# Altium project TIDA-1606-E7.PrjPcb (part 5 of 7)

## Sheet TIDA-1606-Middle-Side-E7.SchDoc
size A2; Date: Not shown in title block; ApprovedBy: Not shown in title block; CheckedBy: Not shown in title block; Author: Not shown in title block; CompanyName: Not shown in title block; Engineer: Not shown in title block; Organization: Not shown in title block; Address1: Not shown in title block; Address2: Not shown in title block; Address3: Not shown in title block; Address4: Not shown in title block; DocumentNumber: 10; Revision: Use project parameter SCH_Rev; SheetNumber: 10; SheetTotal: 16; PageSetup: Record=PageOptions¦CenterHorizontal=True¦CenterVertical=True¦PrintScale=0.69¦XCorrection=1.00¦YCorrection=1.00¦PrintKind=0¦BorderSize=5000000¦LeftOffset=0¦BottomOffset=0¦Orientation=2¦PaperLength=1000¦PaperWidth=1000¦Scale=100¦PaperSource=15¦PrintQuality=600¦MediaType=1¦DitherType=10¦PaperKind=Letter¦PrintScaleMode=1
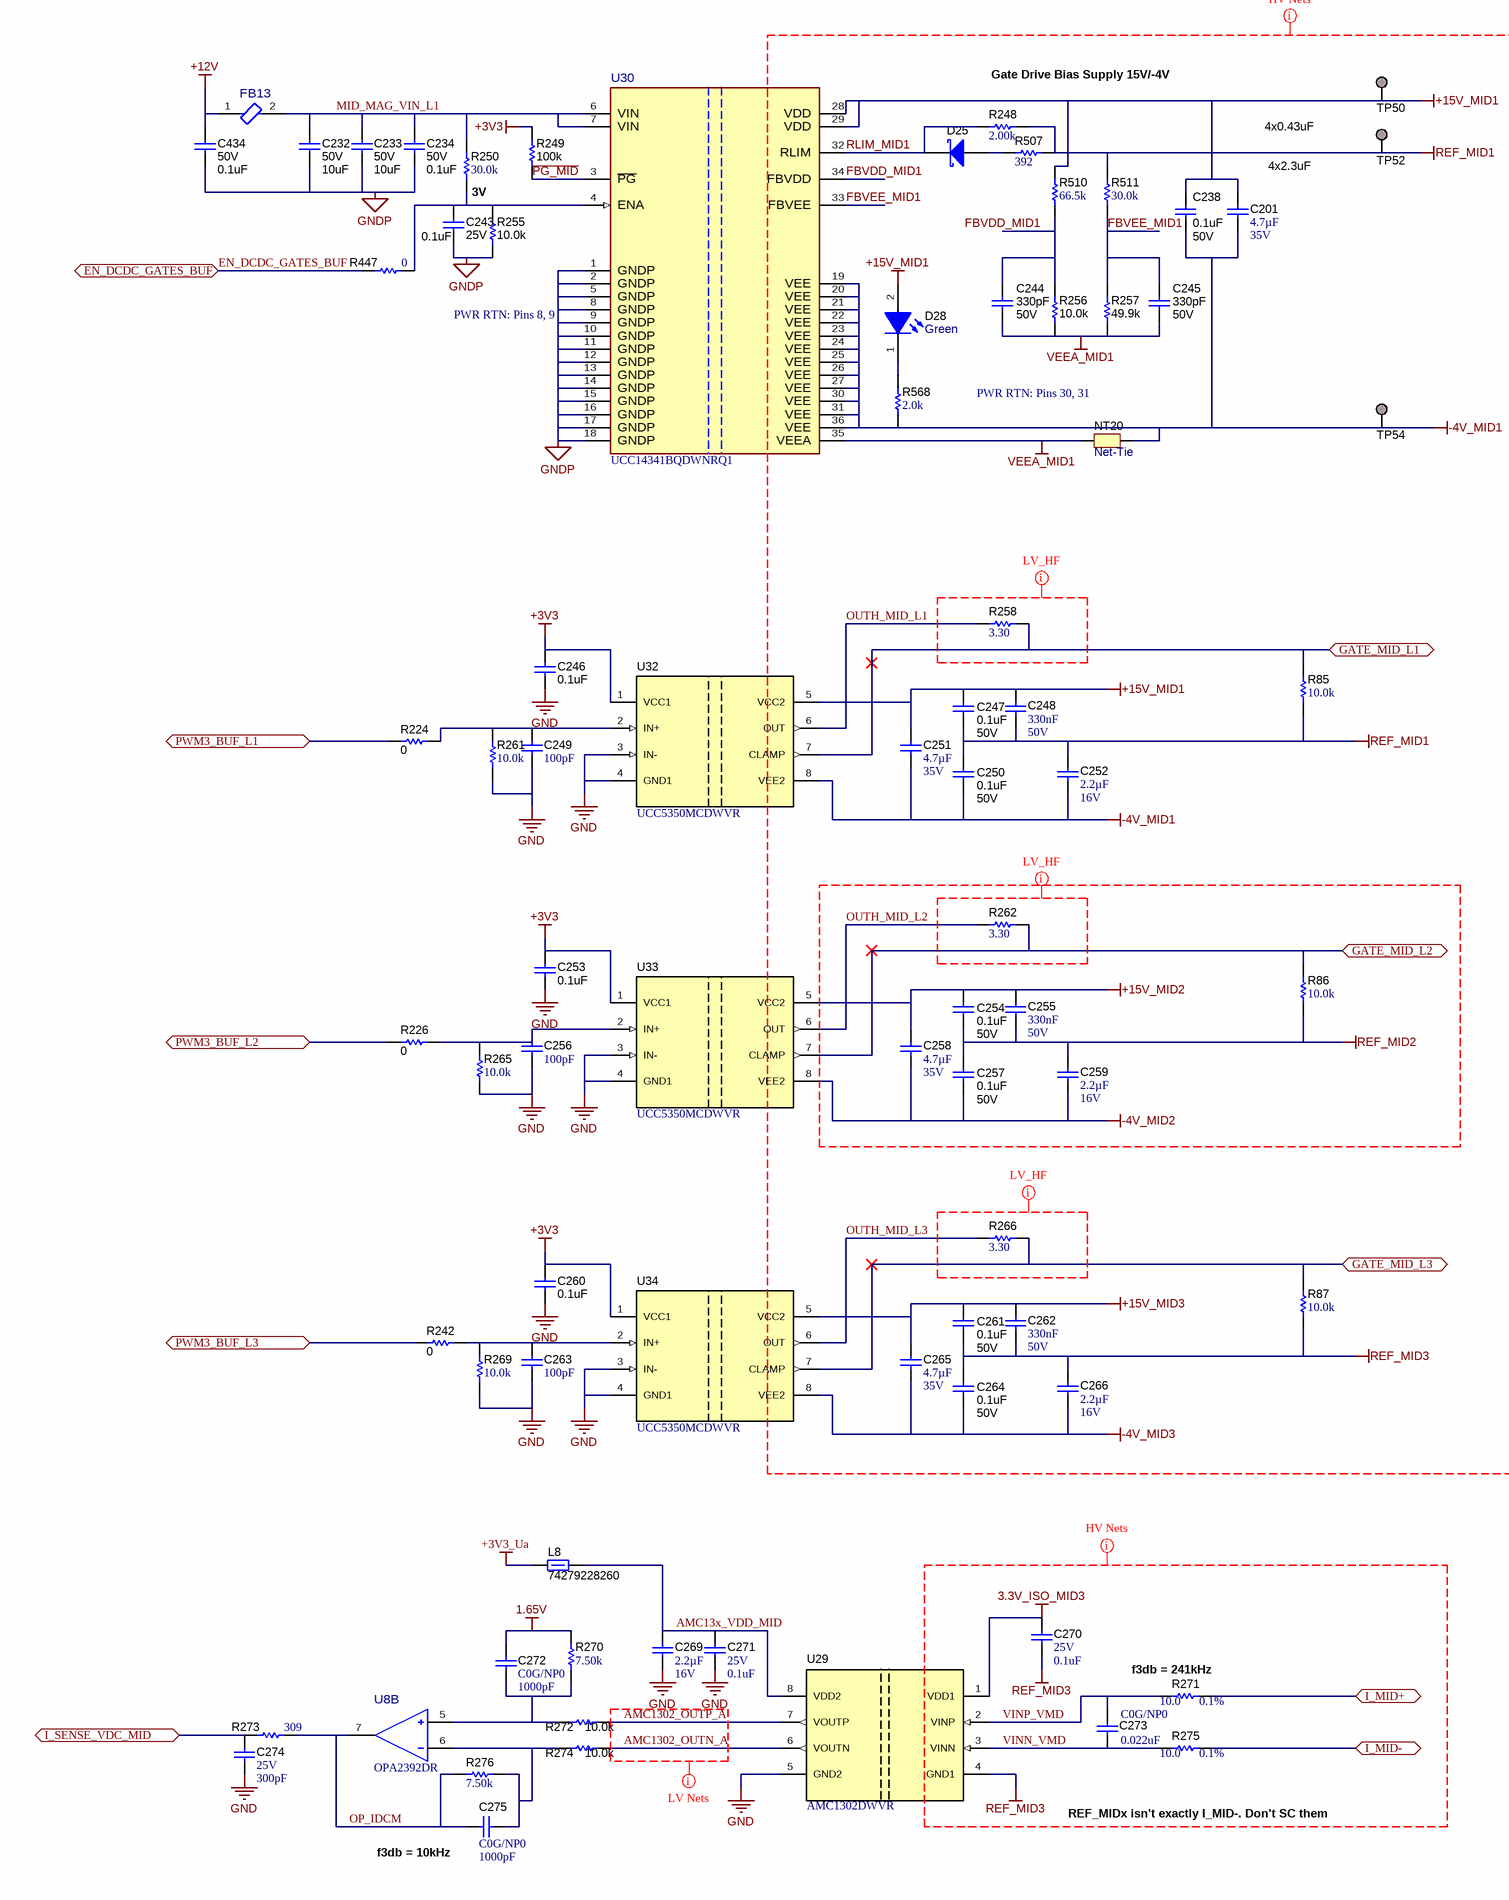
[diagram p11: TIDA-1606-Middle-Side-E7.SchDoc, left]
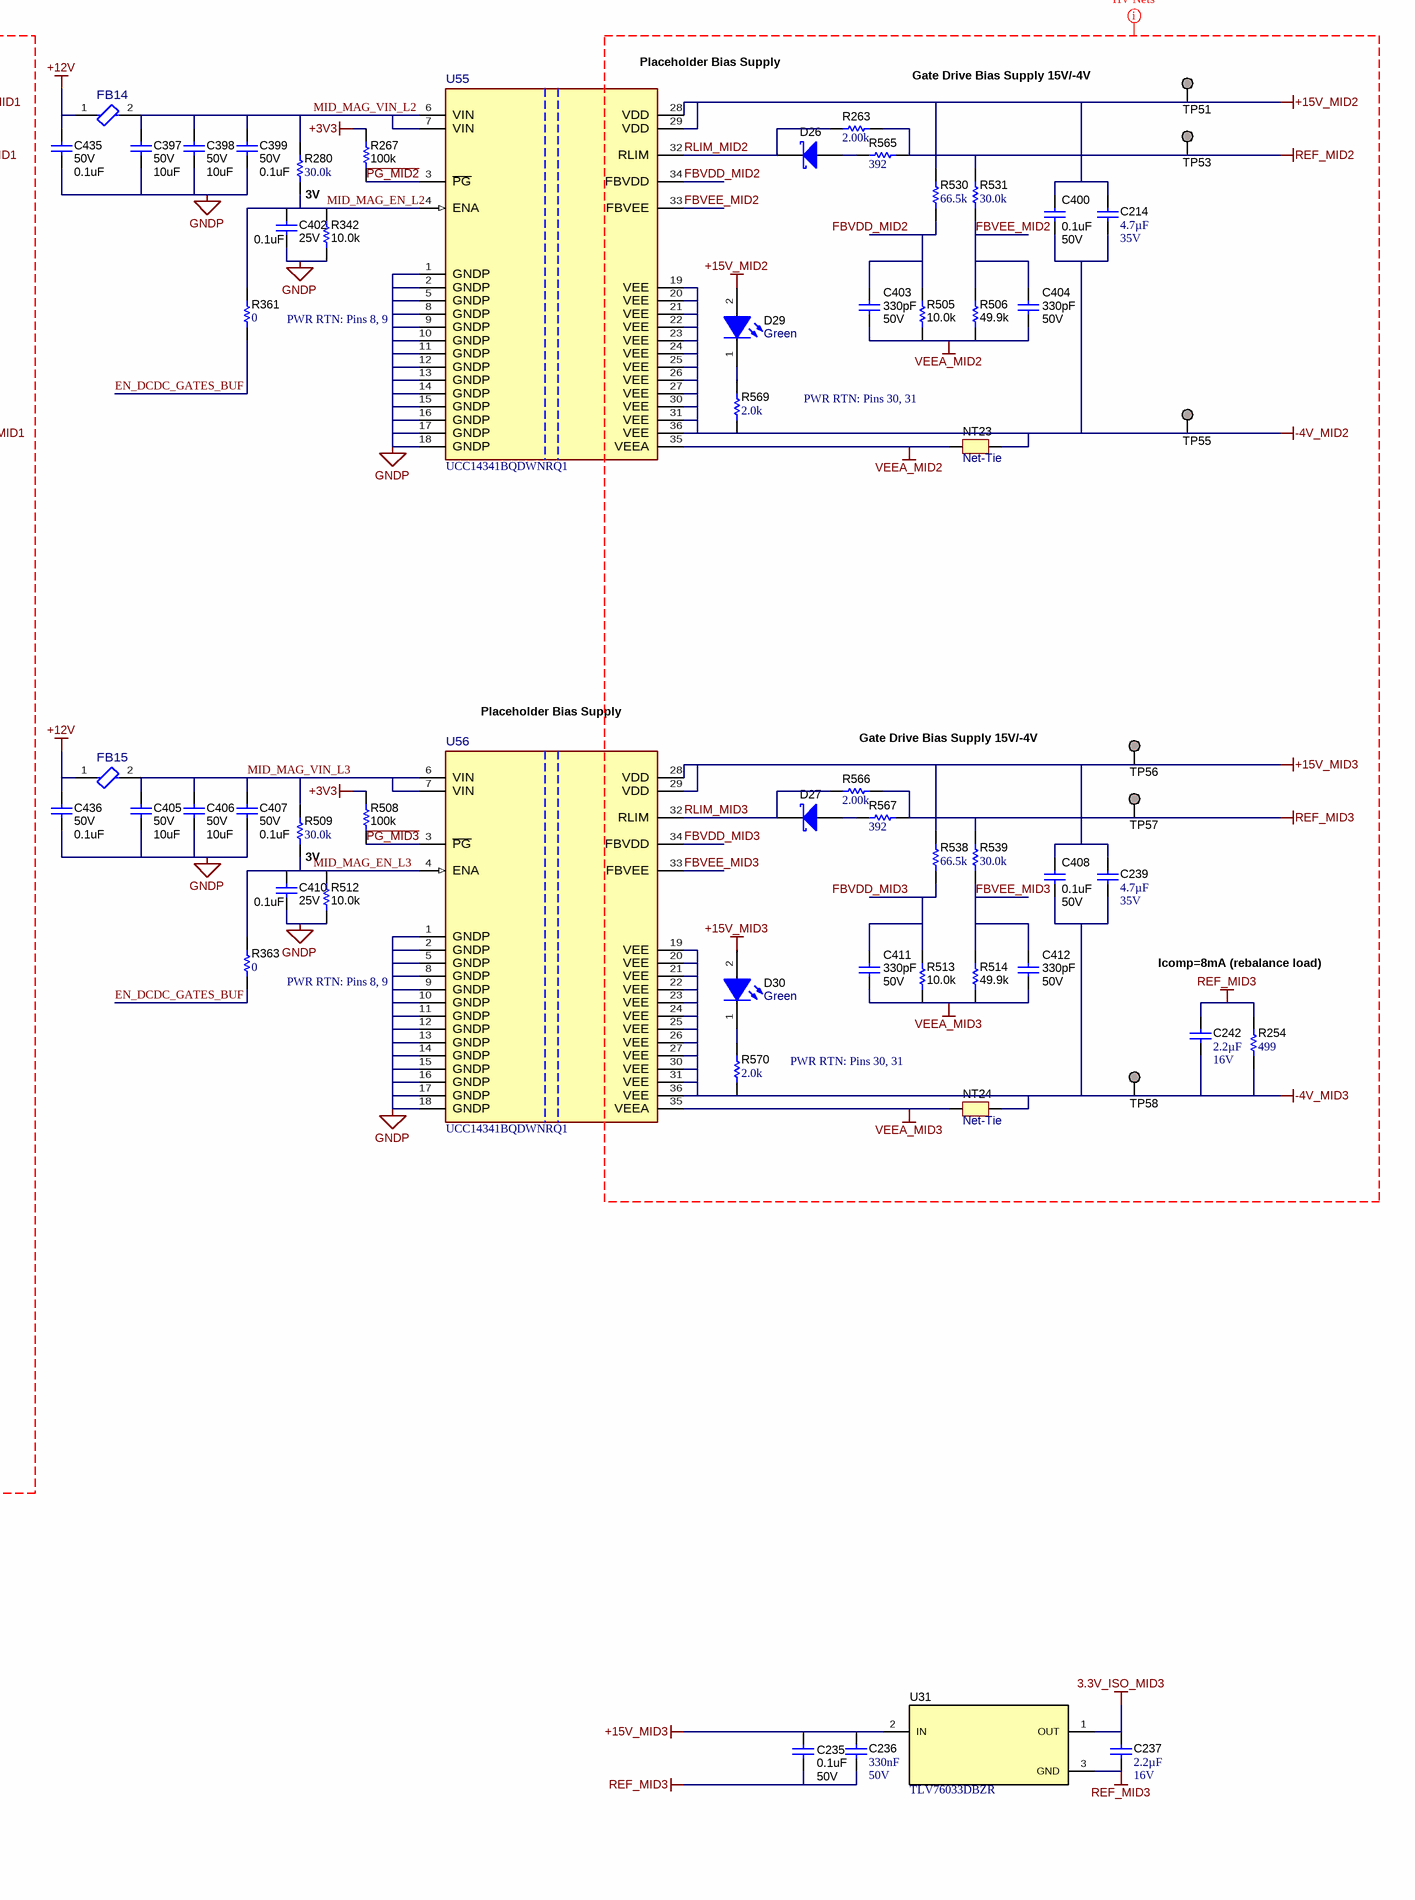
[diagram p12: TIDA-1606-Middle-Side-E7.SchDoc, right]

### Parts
C201  Cap_F: 4.7µF  VDC_V: 35V  [0805_HV]  (hidden comment: C2012X7R1V475K125AC)
C214  Cap_F: 4.7µF  VDC_V: 35V  [0805_HV]  (hidden comment: C2012X7R1V475K125AC)
C232  VDC_V: 50V  ValueDisplayed: 10uF  [1206_180L]  (hidden comment: CL31B106KBHNNNE)
C233  VDC_V: 50V  ValueDisplayed: 10uF  [1206_180L]  (hidden comment: CL31B106KBHNNNE)
C234  VDC_V: 50V  ValueDisplayed: 0.1uF  [0402S]  (hidden comment: GCM155R71H104KE02D)
C235  VDC_V: 50V  ValueDisplayed: 0.1uF  [0402L]  (hidden comment: GCM155R71H104KE02D)
C236  Cap_F: 330nF  VDC_V: 50V  [0603L]  (hidden comment: C1608X7R1H334K080AC)
C237  Cap_F: 2.2µF  VDC_V: 16V  [0603L]  (hidden comment: EMK107BB7225KA-T)
C238  VDC_V: 50V  ValueDisplayed: 0.1uF  [0402L]  (hidden comment: GCM155R71H104KE02D)
C239  Cap_F: 4.7µF  VDC_V: 35V  [0805_HV]  (hidden comment: C2012X7R1V475K125AC)
C242  Cap_F: 2.2µF  VDC_V: 16V  [0603L]  (hidden comment: EMK107BB7225KA-T)
C243  VDC_V: 25V  ValueDisplayed: 0.1uF  [0402S]  (hidden comment: GRM155R71E104KE14D)
C244  VDC_V: 50V  ValueDisplayed: 330pF  [0402S]  (hidden comment: CGA2B2X7R1H331K050BA)
C245  VDC_V: 50V  ValueDisplayed: 330pF  [0402S]  (hidden comment: CGA2B2X7R1H331K050BA)
C246  ValueDisplayed: 0.1uF  [0402L]  (hidden comment: GRM155R61H104ME14D)
C247  VDC_V: 50V  ValueDisplayed: 0.1uF  [0402L]  (hidden comment: GCM155R71H104KE02D)
C248  Cap_F: 330nF  VDC_V: 50V  [0603L]  (hidden comment: C1608X7R1H334K080AC)
C249  ValueDisplayed: 100pF  [0402L]  (hidden comment: GRM1555C1H101JA01D)
C250  VDC_V: 50V  ValueDisplayed: 0.1uF  [0402L]  (hidden comment: GCM155R71H104KE02D)
C251  Cap_F: 4.7µF  VDC_V: 35V  [0805_HV]  (hidden comment: C2012X7R1V475K125AC)
C252  Cap_F: 2.2µF  VDC_V: 16V  [0603L]  (hidden comment: EMK107BB7225KA-T)
C253  ValueDisplayed: 0.1uF  [0402L]  (hidden comment: GRM155R61H104ME14D)
C254  VDC_V: 50V  ValueDisplayed: 0.1uF  [0402L]  (hidden comment: GCM155R71H104KE02D)
C255  Cap_F: 330nF  VDC_V: 50V  [0603L]  (hidden comment: C1608X7R1H334K080AC)
C256  ValueDisplayed: 100pF  [0402L]  (hidden comment: GRM1555C1H101JA01D)
C257  VDC_V: 50V  ValueDisplayed: 0.1uF  [0402L]  (hidden comment: GCM155R71H104KE02D)
C258  Cap_F: 4.7µF  VDC_V: 35V  [0805_HV]  (hidden comment: C2012X7R1V475K125AC)
C259  Cap_F: 2.2µF  VDC_V: 16V  [0603L]  (hidden comment: EMK107BB7225KA-T)
C260  ValueDisplayed: 0.1uF  [0402L]  (hidden comment: GRM155R61H104ME14D)
C261  VDC_V: 50V  ValueDisplayed: 0.1uF  [0402L]  (hidden comment: GCM155R71H104KE02D)
C262  Cap_F: 330nF  VDC_V: 50V  [0603L]  (hidden comment: C1608X7R1H334K080AC)
C263  ValueDisplayed: 100pF  [0402L]  (hidden comment: GRM1555C1H101JA01D)
C264  VDC_V: 50V  ValueDisplayed: 0.1uF  [0402L]  (hidden comment: GCM155R71H104KE02D)
C265  Cap_F: 4.7µF  VDC_V: 35V  [0805_HV]  (hidden comment: C2012X7R1V475K125AC)
C266  Cap_F: 2.2µF  VDC_V: 16V  [0603L]  (hidden comment: EMK107BB7225KA-T)
C269  Cap_F: 2.2µF  VDC_V: 16V  [0603L]  (hidden comment: EMK107BB7225KA-T)
C270  VDC_V: 25V  ValueDisplayed: 0.1uF  [0402L]  (hidden comment: GRM155R71E104KE14D)
C271  VDC_V: 25V  ValueDisplayed: 0.1uF  [0402L]  (hidden comment: GRM155R71E104KE14D)
C272  TempCo: C0G/NP0  ValueDisplayed: 1000pF  [0402L]  (hidden comment: CGA2B2C0G1H102J050BA)
C273  TempCo: C0G/NP0  ValueDisplayed: 0.022uF  [0402L]  (hidden comment: GCM155R71H223KA55D)
C274  VDC_V: 25V  ValueDisplayed: 300pF  [0402L]  (hidden comment: GRM1555C1E301JA01D)
C275  TempCo: C0G/NP0  ValueDisplayed: 1000pF  [0402L]  (hidden comment: CGA2B2C0G1H102J050BA)
C397  VDC_V: 50V  ValueDisplayed: 10uF  [1206_180L]  (hidden comment: CL31B106KBHNNNE)
C398  VDC_V: 50V  ValueDisplayed: 10uF  [1206_180L]  (hidden comment: CL31B106KBHNNNE)
C399  VDC_V: 50V  ValueDisplayed: 0.1uF  [0402S]  (hidden comment: GCM155R71H104KE02D)
C400  VDC_V: 50V  ValueDisplayed: 0.1uF  [0402L]  (hidden comment: GCM155R71H104KE02D)
C402  VDC_V: 25V  ValueDisplayed: 0.1uF  [0402S]  (hidden comment: GRM155R71E104KE14D)
C403  VDC_V: 50V  ValueDisplayed: 330pF  [0402S]  (hidden comment: CGA2B2X7R1H331K050BA)
C404  VDC_V: 50V  ValueDisplayed: 330pF  [0402S]  (hidden comment: CGA2B2X7R1H331K050BA)
C405  VDC_V: 50V  ValueDisplayed: 10uF  [1206_180L]  (hidden comment: CL31B106KBHNNNE)
C406  VDC_V: 50V  ValueDisplayed: 10uF  [1206_180L]  (hidden comment: CL31B106KBHNNNE)
C407  VDC_V: 50V  ValueDisplayed: 0.1uF  [0402S]  (hidden comment: GCM155R71H104KE02D)
C408  VDC_V: 50V  ValueDisplayed: 0.1uF  [0402L]  (hidden comment: GCM155R71H104KE02D)
C410  VDC_V: 25V  ValueDisplayed: 0.1uF  [0402S]  (hidden comment: GRM155R71E104KE14D)
C411  VDC_V: 50V  ValueDisplayed: 330pF  [0402S]  (hidden comment: CGA2B2X7R1H331K050BA)
C412  VDC_V: 50V  ValueDisplayed: 330pF  [0402S]  (hidden comment: CGA2B2X7R1H331K050BA)
C434  VDC_V: 50V  ValueDisplayed: 0.1uF  [0402S]  (hidden comment: GCM155R71H104KE02D)
C435  VDC_V: 50V  ValueDisplayed: 0.1uF  [0402S]  (hidden comment: GCM155R71H104KE02D)
C436  VDC_V: 50V  ValueDisplayed: 0.1uF  [0402S]  (hidden comment: GCM155R71H104KE02D)
D25  NSR0130P2T5G  [SOD-923]  (value not drawn)
D26  NSR0130P2T5G  [SOD-923]  (value not drawn)
D27  NSR0130P2T5G  [SOD-923]  (value not drawn)
D28  value Green  [WL-SMCW_GREEN]  (hidden comment: 150060VS75000)
D29  value Green  [WL-SMCW_GREEN]  (hidden comment: 150060VS75000)
D30  value Green  [WL-SMCW_GREEN]  (hidden comment: 150060VS75000)
FB13  74269244182  [FP-74269244182_0402-MFG]  (value not drawn)
FB14  74269244182  [FP-74269244182_0402-MFG]  (value not drawn)
FB15  74269244182  [FP-74269244182_0402-MFG]  (value not drawn)
L8  74279228260  [0603L]
NT20  Net-Tie  [Net-Tie7milsWide_20milsLong]  (net tie, no BOM)
NT23  Net-Tie  [Net-Tie7milsWide_20milsLong]  (net tie, no BOM)
NT24  Net-Tie  [Net-Tie7milsWide_20milsLong]  (net tie, no BOM)
R85  ValueDisplayed: 10.0k  [0402L]  (hidden comment: CRCW040210K0FKED)
R86  ValueDisplayed: 10.0k  [0402L]  (hidden comment: CRCW040210K0FKED)
R87  ValueDisplayed: 10.0k  [0402L]  (hidden comment: CRCW040210K0FKED)
R224  ValueDisplayed: 0  [0603L]  (hidden comment: RCS06030000Z0EA)
R226  ValueDisplayed: 0  [0603L]  (hidden comment: RCS06030000Z0EA)
R242  ValueDisplayed: 0  [0603L]  (hidden comment: RCS06030000Z0EA)
R248  ValueDisplayed: 2.00k  [0402L]  (hidden comment: CRCW04022K00FKED)
R249  ValueDisplayed: 100k  [0402S]  (hidden comment: ERJ-2GEJ104X)
R250  ValueDisplayed: 30.0k  [0402L]  (hidden comment: CRCW040230K0FKED)
R254  ValueDisplayed: 499  [0805_HV]  (hidden comment: CRCW0805499RFKEA)
R255  ValueDisplayed: 10.0k  [0402S]  (hidden comment: MCS0402MD1002BE100)
R256  ValueDisplayed: 10.0k  [0402S]  (hidden comment: MCS0402MD1002BE100)
R257  ValueDisplayed: 49.9k  [0402S]  (hidden comment: PCF0402-03-49K9BT1)
R258  ValueDisplayed: 3.30  [1206]  (hidden comment: ERJ-8RQF3R3V)
R261  ValueDisplayed: 10.0k  [0402L]  (hidden comment: CRCW040210K0FKED)
R262  ValueDisplayed: 3.30  [1206]  (hidden comment: ERJ-8RQF3R3V)
R263  ValueDisplayed: 2.00k  [0402L]  (hidden comment: CRCW04022K00FKED)
R265  ValueDisplayed: 10.0k  [0402L]  (hidden comment: CRCW040210K0FKED)
R266  ValueDisplayed: 3.30  [1206]  (hidden comment: ERJ-8RQF3R3V)
R267  ValueDisplayed: 100k  [0402S]  (hidden comment: ERJ-2GEJ104X)
R269  ValueDisplayed: 10.0k  [0402L]  (hidden comment: CRCW040210K0FKED)
R270  ValueDisplayed: 7.50k  [0402L]  (hidden comment: ERA-2AEB752X)
R271  Value1: 0.1%  ValueDisplayed: 10.0  [CPF0402]  (hidden comment: CPF0402B10RE1)
R272  ValueDisplayed: 10.0k  [0402L]  (hidden comment: MCS0402MD1002BE100)
R273  ValueDisplayed: 309  [0402L]  (hidden comment: CRCW0402309RFKED)
R274  ValueDisplayed: 10.0k  [0402L]  (hidden comment: MCS0402MD1002BE100)
R275  Value1: 0.1%  ValueDisplayed: 10.0  [CPF0402]  (hidden comment: CPF0402B10RE1)
R276  ValueDisplayed: 7.50k  [0402L]  (hidden comment: ERA-2AEB752X)
R280  ValueDisplayed: 30.0k  [0402L]  (hidden comment: CRCW040230K0FKED)
R342  ValueDisplayed: 10.0k  [0402S]  (hidden comment: MCS0402MD1002BE100)
R361  ValueDisplayed: 0  [0402L]  (hidden comment: RC0402JR-070RL)
R363  ValueDisplayed: 0  [0402L]  (hidden comment: RC0402JR-070RL)
R447  ValueDisplayed: 0  [0402L]  (hidden comment: RC0402JR-070RL)
R505  ValueDisplayed: 10.0k  [0402S]  (hidden comment: MCS0402MD1002BE100)
R506  ValueDisplayed: 49.9k  [0402S]  (hidden comment: PCF0402-03-49K9BT1)
R507  ValueDisplayed: 392  [0402L]  (hidden comment: CRCW0402392RFKED)
R508  ValueDisplayed: 100k  [0402S]  (hidden comment: ERJ-2GEJ104X)
R509  ValueDisplayed: 30.0k  [0402L]  (hidden comment: CRCW040230K0FKED)
R510  ValueDisplayed: 66.5k  [0402L]  (hidden comment: CRCW040266K5FKED)
R511  ValueDisplayed: 30.0k  [0402L]  (hidden comment: CRCW040230K0FKED)
R512  ValueDisplayed: 10.0k  [0402S]  (hidden comment: MCS0402MD1002BE100)
R513  ValueDisplayed: 10.0k  [0402S]  (hidden comment: MCS0402MD1002BE100)
R514  ValueDisplayed: 49.9k  [0402S]  (hidden comment: PCF0402-03-49K9BT1)
R530  ValueDisplayed: 66.5k  [0402L]  (hidden comment: CRCW040266K5FKED)
R531  ValueDisplayed: 30.0k  [0402L]  (hidden comment: CRCW040230K0FKED)
R538  ValueDisplayed: 66.5k  [0402L]  (hidden comment: CRCW040266K5FKED)
R539  ValueDisplayed: 30.0k  [0402L]  (hidden comment: CRCW040230K0FKED)
R565  ValueDisplayed: 392  [0402L]  (hidden comment: CRCW0402392RFKED)
R566  ValueDisplayed: 2.00k  [0402L]  (hidden comment: CRCW04022K00FKED)
R567  ValueDisplayed: 392  [0402L]  (hidden comment: CRCW0402392RFKED)
R568  ValueDisplayed: 2.0k  [1206]  (hidden comment: CRCW12062K00JNEA)
R569  ValueDisplayed: 2.0k  [1206]  (hidden comment: CRCW12062K00JNEA)
R570  ValueDisplayed: 2.0k  [1206]  (hidden comment: CRCW12062K00JNEA)
TP50  S2751-46R  [Harwin_S2751-46R]  (value not drawn)
TP51  S2751-46R  [Harwin_S2751-46R]  (value not drawn)
TP52  S2751-46R  [Harwin_S2751-46R]  (value not drawn)
TP53  S2751-46R  [Harwin_S2751-46R]  (value not drawn)
TP54  S2751-46R  [Harwin_S2751-46R]  (value not drawn)
TP55  S2751-46R  [Harwin_S2751-46R]  (value not drawn)
TP56  S2751-46R  [Harwin_S2751-46R]  (value not drawn)
TP57  S2751-46R  [Harwin_S2751-46R]  (value not drawn)
TP58  S2751-46R  [Harwin_S2751-46R]  (value not drawn)
U8  OPA2392DR  [D0008A-MFG]  (part B of 2)
U29  AMC1302DWVR  [DWV0008A]
U30  UCC14341BQDWNRQ1  [DWN0036A-MFG]
U31  TLV76033DBZR  [DBZ0003A_N]
U32  UCC5350MCDWVR  [DWV0008A]
U33  UCC5350MCDWVR  [DWV0008A]
U34  UCC5350MCDWVR  [DWV0008A]
U55  UCC14341BQDWNRQ1  [DWN0036A-MFG]
U56  UCC14341BQDWNRQ1  [DWN0036A-MFG]

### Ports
EN_DCDC_GATES_BUF (bidir), GATE_MID_L1 (bidir), GATE_MID_L2 (bidir), GATE_MID_L3 (bidir), I_MID+ (bidir), I_MID- (bidir), I_SENSE_VDC_MID (bidir), PWM3_BUF_L1 (bidir), PWM3_BUF_L2 (bidir), PWM3_BUF_L3 (bidir)

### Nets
1.65V: C272.2 R270.2
3.3V_ISO_MID3: C237.1 C270.1 U29.1(VDD1) U31.1(OUT)
+3V3: C246.1 C253.1 C260.1 R249.2 R267.2 R508.2 U32.1(VCC1) U33.1(VCC1) U34.1(VCC1)
+3V3_Ua: L8.1
+12V: C434.1 C435.1 C436.1 FB13.1 FB14.1 FB15.1
+15V_MID1: C201.1 C238.2 C247.2 C248.1 C251.1 D28.2(A) R510.2 TP50.1 U30.28(VDD) U30.29(VDD) U32.5(VCC2)
+15V_MID2: C214.1 C254.2 C255.1 C258.1 C400.2 D29.2(A) R530.2 TP51.1 U33.5(VCC2) U55.28(VDD) U55.29(VDD)
+15V_MID3: C235.2 C236.1 C239.1 C261.2 C262.1 C265.1 C408.2 D30.2(A) R538.2 TP56.1 U31.2(IN) U34.5(VCC2) U56.28(VDD) U56.29(VDD)
-4V_MID1: C201.2 C238.1 C250.1 C251.2 C252.2 NT20.1 R568.1 TP54.1 U30.19(VEE) U30.20(VEE) U30.21(VEE) U30.22(VEE) U30.23(VEE) U30.24(VEE) U30.25(VEE) U30.26(VEE) U30.27(VEE) U30.30(VEE) U30.31(VEE) U30.36(VEE) U32.8(VEE2)
-4V_MID2: C214.2 C257.1 C258.2 C259.2 C400.1 NT23.1 R569.1 TP55.1 U33.8(VEE2) U55.19(VEE) U55.20(VEE) U55.21(VEE) U55.22(VEE) U55.23(VEE) U55.24(VEE) U55.25(VEE) U55.26(VEE) U55.27(VEE) U55.30(VEE) U55.31(VEE) U55.36(VEE)
-4V_MID3: C239.2 C242.2 C264.1 C265.2 C266.2 C408.1 NT24.1 R254.1 R570.1 TP58.1 U34.8(VEE2) U56.19(VEE) U56.20(VEE) U56.21(VEE) U56.22(VEE) U56.23(VEE) U56.24(VEE) U56.25(VEE) U56.26(VEE) U56.27(VEE) U56.30(VEE) U56.31(VEE) U56.36(VEE)
GND: C232.2 C233.2 C234.2 C243.2 C246.2 C249.2 C253.2 C256.2 C260.2 C263.2 C269.2 C271.2 C274.2 C397.2 C398.2 C399.2 C402.2 C405.2 C406.2 C407.2 C410.2 C434.2 C435.2 C436.2 R255.1 R261.2 R265.2 R269.2 R342.1 R512.1 U29.5(GND2) U30.1(GNDP) U30.2(GNDP) U30.5(GNDP) U30.8(GNDP) U30.9(GNDP) U30.10(GNDP) U30.11(GNDP) U30.12(GNDP) U30.13(GNDP) U30.14(GNDP) U30.15(GNDP) U30.16(GNDP) U30.17(GNDP) U30.18(GNDP) U32.3(IN-) U32.4(GND1) U33.3(IN-) U33.4(GND1) U34.3(IN-) U34.4(GND1) U55.1(GNDP) U55.2(GNDP) U55.5(GNDP) U55.8(GNDP) U55.9(GNDP) U55.10(GNDP) U55.11(GNDP) U55.12(GNDP) U55.13(GNDP) U55.14(GNDP) U55.15(GNDP) U55.16(GNDP) U55.17(GNDP) U55.18(GNDP) U56.1(GNDP) U56.2(GNDP) U56.5(GNDP) U56.8(GNDP) U56.9(GNDP) U56.10(GNDP) U56.11(GNDP) U56.12(GNDP) U56.13(GNDP) U56.14(GNDP) U56.15(GNDP) U56.16(GNDP) U56.17(GNDP) U56.18(GNDP)  [also labelled GNDP]
REF_MID1: C247.1 C248.2 C250.2 C252.1 R85.1 R248.1 R507.2 R511.2 TP52.1
REF_MID2: C254.1 C255.2 C257.2 C259.1 R86.1 R263.1 R531.2 R565.2 TP53.1
REF_MID3: C235.1 C236.2 C237.2 C242.1 C261.1 C262.2 C264.2 C266.1 C270.2 R87.1 R254.2 R539.2 R566.1 R567.2 TP57.1 U29.4(GND1) U31.3(GND)
VEEA_MID1: C244.2 C245.2 NT20.2 R256.1 R257.1 U30.35(VEEA)
VEEA_MID2: C403.2 C404.2 NT23.2 R505.1 R506.1 U55.35(VEEA)
VEEA_MID3: C411.2 C412.2 NT24.2 R513.1 R514.1 U56.35(VEEA)
~{PG_MID}: R249.1 U30.3(~{PG})
~{PG_MID2}: R267.1 U55.3(~{PG})
~{PG_MID3}: R508.1 U56.3(~{PG})
AMC13x_VDD_MID: C269.1 C271.1 L8.2 U29.8(VDD2)
AMC1302_OUTN_A: R274.1 U29.6(VOUTN)
AMC1302_OUTP_A: R272.1 U29.7(VOUTP)
EN_DCDC_GATES_BUF: R361.1 R363.1 R447.1 ; port EN_DCDC_GATES_BUF
FBVDD_MID1: C244.1 R256.2 R510.1 U30.34(FBVDD)
FBVDD_MID2: C403.1 R505.2 R530.1 U55.34(FBVDD)
FBVDD_MID3: C411.1 R513.2 R538.1 U56.34(FBVDD)
FBVEE_MID1: C245.1 R257.2 R511.1 U30.33(FBVEE)
FBVEE_MID2: C404.1 R506.2 R531.1 U55.33(FBVEE)
FBVEE_MID3: C412.1 R514.2 R539.1 U56.33(FBVEE)
GATE_MID_L1: R85.2 R258.2 U32.7(CLAMP) ; port GATE_MID_L1
GATE_MID_L2: R86.2 R262.2 U33.7(CLAMP) ; port GATE_MID_L2
GATE_MID_L3: R87.2 R266.2 U34.7(CLAMP) ; port GATE_MID_L3
I_MID+: R271.2 ; port I_MID+
I_MID-: R275.2 ; port I_MID-
I_SENSE_VDC_MID: C274.1 R273.1 ; port I_SENSE_VDC_MID
MID_MAG_EN_L2: C402.1 R280.1 R342.2 R361.2 U55.4(ENA)
MID_MAG_EN_L3: C410.1 R363.2 R509.1 R512.2 U56.4(ENA)
MID_MAG_VIN_L1: C232.1 C233.1 C234.1 FB13.2 R250.2 U30.6(VIN) U30.7(VIN)
MID_MAG_VIN_L2: C397.1 C398.1 C399.1 FB14.2 R280.2 U55.6(VIN) U55.7(VIN)
MID_MAG_VIN_L3: C405.1 C406.1 C407.1 FB15.2 R509.2 U56.6(VIN) U56.7(VIN)
OP_IDCM: C275.2 R273.2 R276.2 U8.7(OUT_B)
OUTH_MID_L1: R258.1 U32.6(OUT)
OUTH_MID_L2: R262.1 U33.6(OUT)
OUTH_MID_L3: R266.1 U34.6(OUT)
PWM3_BUF_L1: R224.2 ; port PWM3_BUF_L1
PWM3_BUF_L2: R226.2 ; port PWM3_BUF_L2
PWM3_BUF_L3: R242.2 ; port PWM3_BUF_L3
RLIM_MID1: D25.1(K) R248.2 U30.32(RLIM)
RLIM_MID2: D26.1(K) R263.2 U55.32(RLIM)
RLIM_MID3: D27.1(K) R566.2 U56.32(RLIM)
VINN_VMD: C273.2 R275.1 U29.3(VINN)
VINP_VMD: C273.1 R271.1 U29.2(VINP)
NetC243_1: C243.1 R250.1 R255.2 R447.2 U30.4(ENA)
NetC249_1: C249.1 R224.1 R261.1 U32.2(IN+)
NetC256_1: C256.1 R226.1 R265.1 U33.2(IN+)
NetC263_1: C263.1 R242.1 R269.1 U34.2(IN+)
NetC272_1: C272.1 R270.1 R272.2 U8.5(+IN_B)
NetC275_1: C275.1 R274.2 R276.1 U8.6(-IN_B)
NetD25_2: D25.2(A) R507.1
NetD26_2: D26.2(A) R565.1
NetD27_2: D27.2(A) R567.1
NetD28_1: D28.1(K) R568.2
NetD29_1: D29.1(K) R569.2
NetD30_1: D30.1(K) R570.2

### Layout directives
net class HV_Nets; net class HV_VDC_MID: 3.3V_ISO_MID3, +15V_MID1, +15V_MID2, +15V_MID3, -4V_MID1, -4V_MID2, -4V_MID3, FBVDD_MID1, FBVDD_MID2, FBVDD_MID3, FBVEE_MID1, FBVEE_MID2, FBVEE_MID3, OUTH_MID_L1, OUTH_MID_L2, OUTH_MID_L3, REF_MID1, REF_MID2, REF_MID3, RLIM_MID1, RLIM_MID2, RLIM_MID3, VEEA_MID1, VEEA_MID2, VEEA_MID3, VINN_VMD, VINP_VMD
net class LV Nets: AMC1302_OUTN_A, AMC1302_OUTP_A
net class LV_HF: (no net found under the mark)

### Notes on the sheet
- (near U55) Placeholder Bias Supply
- Gate Drive Bias Supply 15V/-4V
- 4x0.43uF
- (near R250) 3V
- (near C201) 4x2.3uF
- (near R280) 3V
- PWR RTN: Pins 8, 9
- (near NT20) PWR RTN: Pins 30, 31
- PWR RTN: Pins 30, 31
- Placeholder Bias Supply
- (near R509) 3V
- Icomp=8mA (rebalance load)
- (near R271) f3db = 241kHz
- REF_MIDx isn't exactly I_MID-. Don't SC them
- (near C275) f3db = 10kHz

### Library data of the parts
C201 C214 C239 C251 C258 C265 = CMP-0007885-2: CAP, CERM, 4.7 uF, 35 V, +/- 10%, X7R, 0805; Manufacturer: TDK; TaMin_C: -55°C; ESR_ohm: 2.346m; Polarized: N; SizeAreaWB_mm2: 6.75; Value1: 0.002346 ohm; U/M: EA; Value: 4.7uF; TaMax_C: 125°C; SizeZ_mm: 1.45; SizeX_mm: 2; SizeY_mm: 1.25; Cap_Case: 0805; SizeArea_mm2: 2.5; IRMS_A: 4.26021A; AEC Category: Q200
C232 C233 C397 C398 C405 C406 = CMP-0008802-2: CAP, CERM, 10 uF, 50 V, +/- 10%, X7R, 1206; Manufacturer: Samsung; TaMin_C: -55°C; Polarized: N; SizeAreaWB_mm2: 10.92; Value1: Unknown; U/M: EA; Value: 10uF; TaMax_C: 125°C; SizeZ_mm: 1.8; SizeX_mm: 3.2; SizeY_mm: 1.6; Cap_Case: 1206; SizeArea_mm2: 5.12; Cap_F: 10µF; AEC Category: Q200
C234 C235 C238 C247 C250 C254 C257 C261 C264 C399 C400 C407 C408 C434-C436 = CMP-0006356-2: CAP, CERM, 0.1 uF, 50 V, +/- 10%, X7R, AEC-Q200 Grade 1, 0402; Manufacturer: MuRata; TaMin_C: -55°C; Polarized: N; SizeAreaWB_mm2: 3; Value1: Unknown; U/M: EA; Value: 0.1uF; TaMax_C: 125°C; SizeZ_mm: 0.6; SizeX_mm: 1; SizeY_mm: 0.5; Cap_Case: 0402; AEC Qualified: Y; Cap_F: 100nF; AEC Category: Q200
C236 C248 C255 C262 = CMP-0007048-4: CAP, CERM, 0.33 uF, 50 V, +/- 10%, X7R, 0603; Manufacturer: TDK; TaMin_C: -55°C; ESR_ohm: 0.016574; Polarized: N; SizeAreaWB_mm2: 4.68; Value1: 0.016574 ohm; U/M: EA; Value: 0.33uF; TaMax_C: 125°C; SizeZ_mm: 1; SizeX_mm: 1.6; SizeY_mm: 0.8; Cap_Case: 0603; SizeArea_mm2: 1.28; IRMS_A: 1.28367A; AEC Category: Q200
C237 C242 C252 C259 C266 C269 = CMP-0007121-4: CAP, CERM, 2.2 uF, 16 V, +/- 10%, X7R, 0603; Manufacturer: Taiyo Yuden; TaMin_C: -55°C; Polarized: N; SizeAreaWB_mm2: 4.68; Value1: Unknown; U/M: EA; Value: 2.2uF; TaMax_C: 125°C; SizeZ_mm: 1; SizeX_mm: 1.6; SizeY_mm: 0.8; Cap_Case: 0603; SizeArea_mm2: 1.28; AEC Category: Q200
C243 C270 C271 C402 C410 = CMP-0006659-2: CAP, CERM, 0.1 uF, 25 V, +/- 10%, X7R, 0402; Manufacturer: MuRata; TaMin_C: -55°C; Polarized: N; SizeAreaWB_mm2: 3; Value1: Unknown; U/M: EA; Value: 0.1uF; TaMax_C: 125°C; SizeZ_mm: 0.6; SizeX_mm: 1; SizeY_mm: 0.5; Cap_Case: 0402; Cap_F: 100nF; AEC Category: Q200
C244 C245 C403 C404 C411 C412 = CMP-0006318-2: CAP, CERM, 330 pF, 50 V, +/- 10%, X7R, AEC-Q200 Grade 1, 0402; Manufacturer: TDK; TaMin_C: -55°C; ESR_ohm: 6.53276; Polarized: N; SizeAreaWB_mm2: 3; Value1: 6.53276 ohm; U/M: EA; Value: 330pF; TaMax_C: 125°C; SizeZ_mm: 0.6; SizeX_mm: 1; SizeY_mm: 0.5; Cap_Case: 0402; AEC Qualified: Y; IRMS_A: 2.12649dA; AEC Category: Q200
C246 C253 C260 = CMP-0006614-2: CAP, CERM, 0.1 uF, 50 V, +/- 20%, X5R, 0402; Manufacturer: MuRata; TaMin_C: -55°C; Polarized: N; SizeAreaWB_mm2: 3; Value1: Unknown; U/M: EA; Value: 0.1uF; TaMax_C: 85°C; SizeZ_mm: 0.6; SizeX_mm: 1; SizeY_mm: 0.5; Cap_Case: 0402; Value2: 50V; Cap_F: 100nF; AEC Category: Q200
C249 C256 C263 = CMP-0006410-2: CAP, CERM, 100 pF, 50 V, +/- 5%, C0G/NP0, 0402; Manufacturer: MuRata; TaMin_C: -55°C; Polarized: N; SizeAreaWB_mm2: 3; Value1: Unknown; U/M: EA; Value: 100pF; TaMax_C: 125°C; SizeZ_mm: 0.6; SizeX_mm: 1; SizeY_mm: 0.5; Cap_Case: 0402; Value2: 50V; AEC Category: Q200
C272 C275 = CMP-0006309-2: CAP, CERM, 1000 pF, 50 V, +/- 5%, C0G/NP0, AEC-Q200 Grade 1, 0402; Manufacturer: TDK; TaMin_C: -55°C; Polarized: N; SizeAreaWB_mm2: 3; Value1: Unknown; U/M: EA; Value: 1000pF; TaMax_C: 125°C; SizeZ_mm: 0.6; SizeX_mm: 1; SizeY_mm: 0.5; Cap_Case: 0402; Value2: 50V; AEC Qualified: Y; Cap_F: 1nF; AEC Category: Q200
C273 = CMP-0006358-2: CAP, CERM, 0.022 uF, 50 V, +/- 10%, C0G/NP0, 0402; Manufacturer: MuRata; TaMin_C: -55°C; Polarized: N; SizeAreaWB_mm2: 3; Value1: Unknown; U/M: EA; TaMax_C: 125°C; SizeZ_mm: 0.6; SizeX_mm: 1; SizeY_mm: 0.5; Cap_Case: 0402; Value2: 50V; Cap_F: 22nF; AEC Category: Q200
C274 = CMP-0006376-2: CAP, CERM, 300 pF, 25 V, +/- 5%, C0G/NP0, 0402; Manufacturer: MuRata; TaMin_C: -55°C; Polarized: N; SizeAreaWB_mm2: 3; Value1: Unknown; U/M: EA; Value: 300pF; TaMax_C: 125°C; SizeZ_mm: 0.6; SizeX_mm: 1; SizeY_mm: 0.5; Cap_Case: 0402; AEC Category: Q200
D25-D27 = CMP-0077005-2: Diode, Schottky, 30 V, 0.1 A, SOD-923; Manufacturer: ON Semiconductor; AEC Category: Q101; Value1: 0.1A; SizeZ_mm: 0.4; Vr_V: 30V; Vf_V: 525mV; SizeX_mm: 1.0; Value2: 0.525V; SizeY_mm: 0.6; Green_Lifecycle: Not Set; TJmax_C: 125°C; Value: 30V; Io_A: 100mA; SizeAreaWB_mm2: 3.2; Green_REACh: Incomplete
D28-D30 = CMP-0002894-2: LED, Green, SMD; Manufacturer: Wurth Elektronik; Type: AlInGaP; Value2: 2V; Io_A: 20mA; Value1: W
FB13-FB15 = CMP-0091663-1: 1.8 kOhms @ 100MHz 1 Power, Signal Line Ferrite Bead 0402 (1005 Metric) 210mA 2.1Ohm; Manufacturer: Wurth Electronics; SizeZ_mm: 0.55mm; AEC Qualified: No; DCR_ohm: 2.1; Tolerance_%: 25%; Test Frequency: 1GHz; Impedance At Frequency: 1800Ω @ 100MHz
L8 = CMP-0003155-2: Ferrite Bead, 26 ohm @ 100 MHz, 6.5 A, 0603; Manufacturer: Wurth Elektronik; Ztyp@1GHz_Ohm: 35.506; ZTyp@100MHz_Ohm: 26; SizeAreaWB_mm2: 4.68; DCR_ohm: 5m; Value1: 0.005 ohm; Value: 26 ohm; Imax_A: 6.5A; SizeZ_mm: 1; SizeX_mm: 1.6; SizeY_mm: 0.8; SizeArea_mm2: 1.28
NT20 NT23 NT24 = CMP-0078142-6: Single point connection between nets.
R85-R87 R261 R265 R269 = CMP-0025958-3: RES, 10.0 k, 1%, 0.063 W, AEC-Q200 Grade 0, 0402; Manufacturer: Vishay-Dale; Power_W: 63mW; TempCo: 100 ppm/C; Value_Code: 10k0; Value: 10.0k; EIA_Code: E96; Res_ohm: 10k; SizeX_mm: 1; SizeY_mm: 0.5; SizeZ_mm: 0.6; Value2: 0.063W; AEC Qualified: Y; VDC_V: 50V; AEC Category: Q200; AEC Grade: 0
R224 R226 R242 = CMP-0081973-1: RES, 0, 0%, 0.25 W, AEC-Q200 Grade 0, 0603; Manufacturer: Vishay-Dale; SizeAreaWB_mm2: 4.68; SizeArea_mm2: 1.28; AEC Qualified: Y; AEC Category: Q200; Value: 0; SizeZ_mm: 1; SizeY_mm: 0.8; Power_W: 250mW; Value2: 0.25W; SizeX_mm: 1.6
R248 R263 R566 = CMP-0026227-2: RES, 2.00 k, 1%, 0.063 W, AEC-Q200 Grade 0, 0402; Manufacturer: Vishay-Dale; Power_W: 63mW; TempCo: 100 ppm/C; Value_Code: 2k00; Value: 2.00k; EIA_Code: E96; Res_ohm: 2k; SizeX_mm: 1; SizeY_mm: 0.5; SizeZ_mm: 0.6; Value2: 0.063W; AEC Qualified: Y; VDC_V: 50V; AEC Category: Q200; AEC Grade: 0
R249 R267 R508 = CMP-0026995-2: RES, 100 k, 5%, 0.1 W, AEC-Q200 Grade 0, 0402; Manufacturer: Panasonic; Power_W: 100mW; TempCo: 200 ppm/C; U/M: EA; Value: 100k; EIA_Code: E24; SizeX_mm: 1; SizeY_mm: 0.5; SizeZ_mm: 0.6; Value2: 0.1W; AEC Qualified: Y; VDC_V: 50V; AEC Grade: 0; AEC Category: Q200
R250 R280 R509 R511 R531 R539 = CMP-0078244-2: RES, 30.0 k, 1%, 0.063 W, AEC-Q200 Grade 0, 0402; Manufacturer: Vishay-Dale; Power_W: 63mW; Green_Lifecycle: Active; TempCo: 100 ppm/C; Value_Code: 30k0; Green_REACh: Passed; Value: 30.0k; Res_ohm: 30k; SizeX_mm: 1; SizeY_mm: 0.5; SizeZ_mm: 0.6; Value2: 0.063W; AEC Qualified: Y; VDC_V: 50V; AEC Grade: 0; AEC Category: Q200
R254 = CMP-0021282-3: RES, 499, 1%, 0.125 W, AEC-Q200 Grade 0, 0805; Manufacturer: Vishay-Dale; Power_W: 125mW; TempCo: 100 ppm/C; Value_Code: 499R; Value: 499; EIA_Code: E96; SizeX_mm: 2; SizeY_mm: 1.25; SizeZ_mm: 1.45; Value2: 0.125W; SizeArea_mm2: 2.5; AEC Qualified: Y; VDC_V: 150V; AEC Category: Q200; AEC Grade: 0
R255 R256 R272 R274 R342 R505 R512 R513 = CMP-0077124-1: RES, 10.0 k, 0.1%, 0.1 W, AEC-Q200 Grade 0, 0402; Manufacturer: Vishay/Beyschlag; Value_Code: 10k0; SizeArea_mm2: 0.5; AEC Qualified: Y; AEC Category: Q200; Res_ohm: 10k; Value: 10.0k; SizeZ_mm: 0.6; EIA_Code: E192; TempCo: 25 ppm/C; AEC Grade: 0; Power_W: 100mW; VDC_V: 50V; Value2: 0.1W; U/M: EA; SizeX_mm: 1.0
R257 R506 R514 = CMP-0026795-1: RES, 49.9 k, 0.1%, 0.063 W, 0402; Manufacturer: TT Electronics/IRC; Power_W: 63mW; TempCo: 25 ppm/C; Value_Code: 49k9; U/M: EA; Value: 49.9k; EIA_Code: E192; SizeX_mm: 1; SizeY_mm: 0.5; SizeZ_mm: 0.6; Value2: 0.063W; AEC Qualified: N; VDC_V: 25V; AEC Category: Q200
R258 R262 R266 = CMP-0017779-3: RES, 3.30, 1%, 0.25 W, AEC-Q200 Grade 0, 1206; Manufacturer: Panasonic; Power_W: 250mW; TempCo: 200 ppm/C; Value_Code: 3R30; Value: 3.30; Res_ohm: 3.3; SizeX_mm: 3.2; SizeY_mm: 1.6; SizeZ_mm: 1.35; Value2: 0.25W; SizeArea_mm2: 5.12; AEC Qualified: Y; AEC Category: Q200; AEC Grade: 0; SizeAreaWB_mm2: 10.92
R270 R276 = CMP-0026786-1: RES, 7.50 k, 0.1%, 0.063 W, AEC-Q200 Grade 0, 0402; Manufacturer: Panasonic; Power_W: 63mW; TempCo: 25 ppm/C; Value_Code: 7k50; U/M: EA; Value: 7.50k; EIA_Code: E192; Res_ohm: 7.5k; SizeX_mm: 1; SizeY_mm: 0.5; SizeZ_mm: 0.6; Value2: 0.063W; AEC Qualified: Y; VDC_V: 50V; AEC Grade: 0; AEC Category: Q200
R271 R275 = CMP-0026765-1: RES, 10.0, 0.1%, 0.063 W, 0402; Manufacturer: TE Connectivity; Power_W: 63mW; TempCo: 25 ppm/C; Value_Code: 10R0; U/M: EA; Value: 10.0; EIA_Code: E192; Res_ohm: 10; SizeX_mm: 1; SizeY_mm: 0.5; SizeZ_mm: 0.35; Value2: 0.063W; AEC Qualified: N; AEC Category: Q200
R273 = CMP-0026283-2: RES, 309, 1%, 0.063 W, AEC-Q200 Grade 0, 0402; Manufacturer: Vishay-Dale; Power_W: 63mW; TempCo: 100 ppm/C; Value_Code: 309R; Value: 309; EIA_Code: E96; SizeX_mm: 1; SizeY_mm: 0.5; SizeZ_mm: 0.6; Value2: 0.063W; AEC Qualified: Y; VDC_V: 50V; AEC Category: Q200; AEC Grade: 0
R361 R363 R447 = CMP-0027004-2: RES, 0, 5%, 0.063 W, 0402; Manufacturer: Yageo America; Power_W: 63mW; TempCo: 200 ppm/C; Value_Code: 0000; U/M: EA; Value: 0; EIA_Code: E24; SizeX_mm: 1; SizeY_mm: 0.5; SizeZ_mm: 0.6; Value2: 0.063W; VDC_V: 50V; AEC Category: Q200
R507 R565 R567 = CMP-0026326-2: RES, 392, 1%, 0.063 W, AEC-Q200 Grade 0, 0402; Manufacturer: Vishay-Dale; Power_W: 63mW; TempCo: 100 ppm/C; Value_Code: 392R; Value: 392; EIA_Code: E96; SizeX_mm: 1; SizeY_mm: 0.5; SizeZ_mm: 0.6; Value2: 0.063W; AEC Qualified: Y; VDC_V: 50V; AEC Category: Q200; AEC Grade: 0
R510 R530 R538 = CMP-0026502-2: RES, 66.5 k, 1%, 0.063 W, AEC-Q200 Grade 0, 0402; Manufacturer: Vishay-Dale; Power_W: 63mW; TempCo: 100 ppm/C; Value_Code: 66k5; Value: 66.5k; EIA_Code: E96; SizeX_mm: 1; SizeY_mm: 0.5; SizeZ_mm: 0.6; Value2: 0.063W; AEC Qualified: Y; VDC_V: 50V; AEC Category: Q200; AEC Grade: 0
R568-R570 = CMP-0018640-3: RES, 2.0 k, 5%, 0.25 W, AEC-Q200 Grade 0, 1206; Manufacturer: Vishay-Dale; Power_W: 250mW; TempCo: 200 ppm/C; Value_Code: 2k00; Value: 2.0k; EIA_Code: E24; Res_ohm: 2k; SizeX_mm: 3.2; SizeY_mm: 1.6; SizeZ_mm: 1.35; Value2: 0.25W; SizeArea_mm2: 5.12; AEC Qualified: Y; VDC_V: 200V; AEC Category: Q200; AEC Grade: 0
TP50-TP58 = CMP-0003968-1: Test Point, SMT; Manufacturer: Harwin
U8 = CMP-0121707-1: Precision, Low-Offset-Voltage, Low-Noise, Low-Input-Bias-Current, Rail-to-Rail I/O, e-trim™ Operational Amplifiers; Manufacturer: Texas Instruments; SizeZ_mm: 1.75mm; AEC Qualified: No; Gain Bandwidth: 13MHz; Input Bias Current: 0.00000001uA; Input Offset Voltage: 0.001mV; Max Dual Supply Voltage: 2.75V; Max Supply Voltage: 5.5V; Min Dual Supply Voltage: 850mV; Min Supply Voltage: 1.7V; Nominal Supply Current: 1.22mA; Number Of Channels: 2; Output Current Per Channel: 65mA; Response Time: 1us; Standoff Height: 0.11mm; TaMax_C: +125°C; TaMin_C: -40°C; TJmax_C: +150°C; Voltage Gain: 132dB
U29 = CMP-0080672-1: Precision Reinforced Isolated Amplifier for Current Sensing, DWV0008A (SOIC-8); Alternate Manufacturer: Texas Instruments; SizeAreaWB_mm2: 105.975; SizeZ_mm: 2.8; SizeX_mm: 11.5; SizeY_mm: 5.85; SizeArea_mm2: 67.275; CompType: IC; AEC Qualified: N; AEC Category: Q200
U30 U55 U56 = CMP-0121477-1: Automotive 1.5-W, 15-V VIN, 25-V VOUT, High-Density, > 5 kVRMS, Isolated DC/DC Module; Manufacturer: Texas Instruments; SizeZ_mm: 3.55mm; AEC Qualified: Yes; AEC Grade: Grade 1; Max Supply Voltage: 16.5V; Min Supply Voltage: 13.5V; Nominal Supply Current: 190mA; Number Of Outputs: 1; Output Type: AdjustableProgrammable; Output Voltage: 15-25V; Standoff Height: 0.1mm; Switching Frequency: 15MHz; TaMax_C: +125°C; TaMin_C: -40°C; TJmax_C: +150°C
U31 = CMP-0074893-1: 100-mA, 30-V, Fixed-Output, Linear-Voltage Regulator, DBZ0003A (SOT-23-3); Alternate PartNumber: TLV76033DBZT; Alternate Manufacturer: Texas Instruments; SizeAreaWB_mm2: 14.0; SizeZ_mm: 1.12; SizeX_mm: 2.5; SizeY_mm: 3.0; SizeArea_mm2: 7.5; CompType: IC; AEC Qualified: N; AEC Category: Q200
U32-U34 = CMP-0078841-1: 5-kVRMS Single-Channel Isolated Gate Drivers, DWV0008A (SOIC-8); Alternate Manufacturer: Texas Instruments; SizeAreaWB_mm2: 105.975; SizeZ_mm: 2.8; SizeX_mm: 11.5; SizeY_mm: 5.85; SizeArea_mm2: 67.275; CompType: IC; AEC Qualified: N; AEC Category: Q200

## Sheet TIDA-1606-DC-Voltage-Measurements-E7-.SchDoc
size 431 x 279 mm; Date: Not shown in title block; ApprovedBy: Not shown in title block; CheckedBy: Not shown in title block; Author: Not shown in title block; CompanyName: Not shown in title block; Engineer: Not shown in title block; Organization: Not shown in title block; Address1: Not shown in title block; Address2: Not shown in title block; Address3: Not shown in title block; Address4: Not shown in title block; DocumentNumber: 8; Revision: Use project parameter SCH_Rev; SheetNumber: 8; SheetTotal: 16; PageSetup: Record=PageOptions¦CenterHorizontal=True¦CenterVertical=True¦PrintScale=1.00¦XCorrection=1.00¦YCorrection=1.00¦PrintKind=0¦BorderSize=5000000¦LeftOffset=0¦BottomOffset=0¦Orientation=2¦PaperLength=1000¦PaperWidth=1000¦Scale=100¦PaperSource=15¦PrintQuality=600¦MediaType=1¦DitherType=10¦PaperKind=Letter¦PrintScaleMode=1
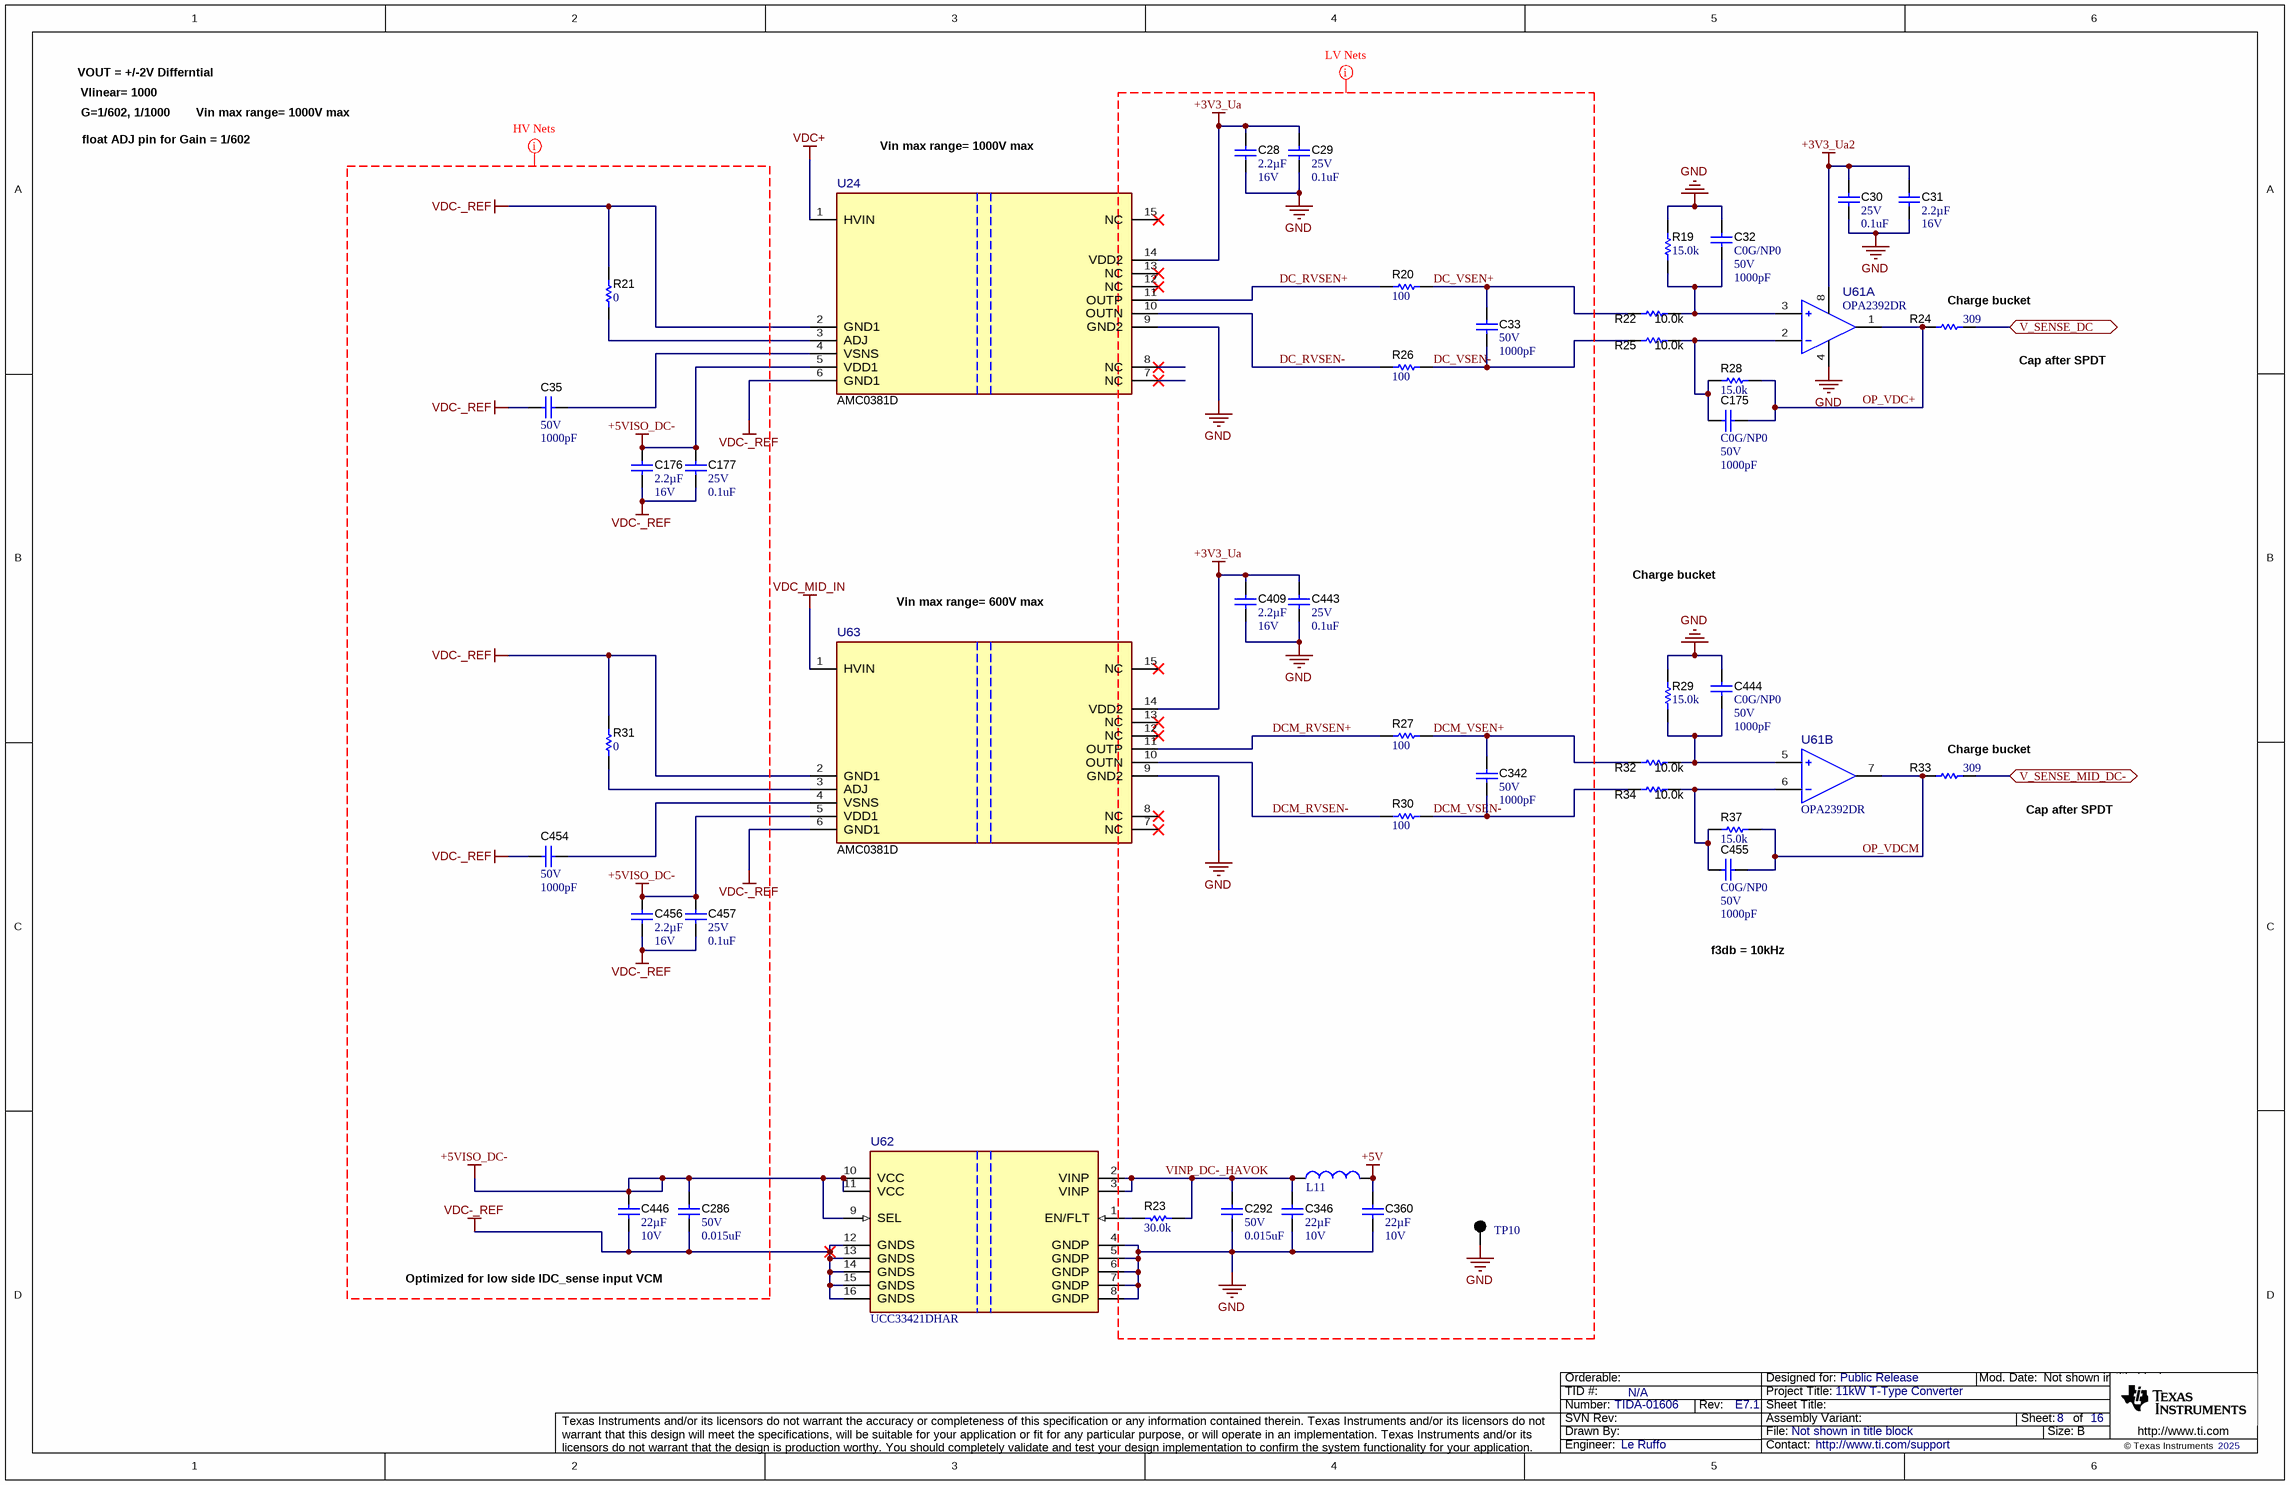
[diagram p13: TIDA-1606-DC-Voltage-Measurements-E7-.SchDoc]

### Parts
C28  Cap_F: 2.2µF  VDC_V: 16V  [0603]  (hidden comment: EMK107BB7225KA-T)
C29  VDC_V: 25V  ValueDisplayed: 0.1uF  [0402L]  (hidden comment: GRM155R71E104KE14D)
C30  VDC_V: 25V  ValueDisplayed: 0.1uF  [0402L]  (hidden comment: GRM155R71E104KE14D)
C31  Cap_F: 2.2µF  VDC_V: 16V  [0603]  (hidden comment: EMK107BB7225KA-T)
C32  TempCo: C0G/NP0  VDC_V: 50V  ValueDisplayed: 1000pF  [0402L]  (hidden comment: CGA2B2C0G1H102J050BA)
C33  VDC_V: 50V  ValueDisplayed: 1000pF  [0402L]  (hidden comment: GRM1555C1H102JA01D)
C35  VDC_V: 50V  ValueDisplayed: 1000pF  [0402L]  (hidden comment: GRM155R71H102KA01D)
C175  TempCo: C0G/NP0  VDC_V: 50V  ValueDisplayed: 1000pF  [0402L]  (hidden comment: CGA2B2C0G1H102J050BA)
C176  Cap_F: 2.2µF  VDC_V: 16V  [0603]  (hidden comment: EMK107BB7225KA-T)
C177  VDC_V: 25V  ValueDisplayed: 0.1uF  [0402L]  (hidden comment: GRM155R71E104KE14D)
C286  VDC_V: 50V  ValueDisplayed: 0.015uF  [0402L]  (hidden comment: CGA2B3X7R1H153K050BB)
C292  VDC_V: 50V  ValueDisplayed: 0.015uF  [0402L]  (hidden comment: CGA2B3X7R1H153K050BB)
C342  VDC_V: 50V  ValueDisplayed: 1000pF  [0402L]  (hidden comment: GRM1555C1H102JA01D)
C346  Cap_F: 22µF  VDC_V: 10V  [0805_HV]  (hidden comment: GRM21BZ71A226ME15L)
C360  Cap_F: 22µF  VDC_V: 10V  [0805_HV]  (hidden comment: GRM21BZ71A226ME15L)
C409  Cap_F: 2.2µF  VDC_V: 16V  [0603]  (hidden comment: EMK107BB7225KA-T)
C443  VDC_V: 25V  ValueDisplayed: 0.1uF  [0402L]  (hidden comment: GRM155R71E104KE14D)
C444  TempCo: C0G/NP0  VDC_V: 50V  ValueDisplayed: 1000pF  [0402L]  (hidden comment: CGA2B2C0G1H102J050BA)
C446  Cap_F: 22µF  VDC_V: 10V  [0805_HV]  (hidden comment: GRM21BZ71A226ME15L)
C454  VDC_V: 50V  ValueDisplayed: 1000pF  [0402L]  (hidden comment: GRM155R71H102KA01D)
C455  TempCo: C0G/NP0  VDC_V: 50V  ValueDisplayed: 1000pF  [0402L]  (hidden comment: CGA2B2C0G1H102J050BA)
C456  Cap_F: 2.2µF  VDC_V: 16V  [0603]  (hidden comment: EMK107BB7225KA-T)
C457  VDC_V: 25V  ValueDisplayed: 0.1uF  [0402L]  (hidden comment: GRM155R71E104KE14D)
L11  74479763222  [WE-PMI_0603_L1.6W0.8H0.8]  (value not drawn)
R19  ValueDisplayed: 15.0k  [0402L]  (hidden comment: ERA-2AEB153X)
R20  ValueDisplayed: 100  [0402L]  (hidden comment: ERJ-2RKF1000X)
R21  ValueDisplayed: 0  [0402L]  (hidden comment: RC0402JR-070RL)
R22  ValueDisplayed: 10.0k  [0402L]  (hidden comment: MCS0402MD1002BE100)
R23  ValueDisplayed: 30.0k  [0402L]  (hidden comment: CRCW040230K0FKED)
R24  ValueDisplayed: 309  [0402L]  (hidden comment: CRCW0402309RFKED)
R25  ValueDisplayed: 10.0k  [0402L]  (hidden comment: MCS0402MD1002BE100)
R26  ValueDisplayed: 100  [0402L]  (hidden comment: ERJ-2RKF1000X)
R27  ValueDisplayed: 100  [0402L]  (hidden comment: ERJ-2RKF1000X)
R28  ValueDisplayed: 15.0k  [0402L]  (hidden comment: ERA-2AEB153X)
R29  ValueDisplayed: 15.0k  [0402L]  (hidden comment: ERA-2AEB153X)
R30  ValueDisplayed: 100  [0402L]  (hidden comment: ERJ-2RKF1000X)
R31  ValueDisplayed: 0  [0402L]  (hidden comment: RC0402JR-070RL)
R32  ValueDisplayed: 10.0k  [0402L]  (hidden comment: MCS0402MD1002BE100)
R33  ValueDisplayed: 309  [0402L]  (hidden comment: CRCW0402309RFKED)
R34  ValueDisplayed: 10.0k  [0402L]  (hidden comment: MCS0402MD1002BE100)
R37  ValueDisplayed: 15.0k  [0402L]  (hidden comment: ERA-2AEB153X)
TP10  5011  [Keystone5011]  (value not drawn)
U24  AMC0381D  [DFX0015A-MFG]
U61  OPA2392DR  [D0008A-MFG]  (parts A,B of 2)
U62  UCC33421DHAR  [DHA0016A-MFG]
U63  AMC0381D  [DFX0015A-MFG]

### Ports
V_SENSE_DC (bidir), V_SENSE_MID_DC- (bidir)

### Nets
+3V3_Ua: C28.2 C29.1 C409.2 C443.1 U24.14(VDD2) U63.14(VDD2)
+3V3_Ua2: C30.1 C31.1 U61.8(V+)
+5V: C360.1 L11.2
+5VISO_DC-: C176.2 C177.1 C286.1 C446.1 C456.2 C457.1 U24.5(VDD1) U62.9(SEL) U62.10(VCC) U62.11(VCC) U63.5(VDD1)
GND: C28.1 C29.2 C30.2 C31.2 C32.1 C292.2 C346.2 C360.2 C409.1 C443.2 C444.1 R19.2 R29.2 TP10.1 U24.9(GND2) U61.4(V-) U62.4(GNDP) U62.5(GNDP) U62.6(GNDP) U62.7(GNDP) U62.8(GNDP) U63.9(GND2)
VDC+: U24.1(HVIN)
VDC-_REF: C35.1 C176.1 C177.2 C286.2 C446.2 C454.1 C456.1 C457.2 R21.2 R31.2 U24.2(GND1) U24.6(GND1) U62.12(GNDS) U62.13(GNDS) U62.14(GNDS) U62.15(GNDS) U62.16(GNDS) U63.2(GND1) U63.6(GND1)
VDC_MID_IN: U63.1(HVIN)
DC_RVSEN+: R20.1 U24.11(OUTP)
DC_RVSEN-: R26.1 U24.10(OUTN)
DC_VSEN+: C33.1 R20.2 R22.2
DC_VSEN-: C33.2 R25.2 R26.2
DCM_RVSEN+: R27.1 U63.11(OUTP)
DCM_RVSEN-: R30.1 U63.10(OUTN)
DCM_VSEN+: C342.1 R27.2 R32.2
DCM_VSEN-: C342.2 R30.2 R34.2
OP_VDC+: C175.2 R24.1 R28.2 U61.1(OUT_A)
OP_VDCM: C455.2 R33.1 R37.2 U61.7(OUT_B)
V_SENSE_DC: R24.2 ; port V_SENSE_DC
V_SENSE_MID_DC-: R33.2 ; port V_SENSE_MID_DC-
VINP_DC-_HAVOK: C292.1 C346.1 L11.1 R23.1 U62.2(VINP) U62.3(VINP)
NetC32_2: C32.2 R19.1 R22.1 U61.3(+IN_A)
NetC35_2: C35.2 U24.4(VSNS)
NetC175_1: C175.1 R25.1 R28.1 U61.2(-IN_A)
NetC444_2: C444.2 R29.1 R32.1 U61.5(+IN_B)
NetC454_2: C454.2 U63.4(VSNS)
NetC455_1: C455.1 R34.1 R37.1 U61.6(-IN_B)
NetR21_1: R21.1 U24.3(ADJ)
NetR23_2: R23.2 U62.1(EN/FLT)
NetR31_1: R31.1 U63.3(ADJ)

Not connected (* = marked no-connect by the designer): U24 7(NC)* 8(NC)* 12(NC)* 13(NC)* 15(NC)*; U63 7(NC)* 8(NC)* 12(NC)* 13(NC)* 15(NC)*

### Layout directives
net class LV Nets: +3V3_Ua, +5V, DC_RVSEN+, DC_RVSEN-, DC_VSEN+, DC_VSEN-, DCM_RVSEN+, DCM_RVSEN-, DCM_VSEN+, DCM_VSEN-, GND, VINP_DC-_HAVOK
net class HV_Nets; net class HV_VDC_LOW: +5VISO_DC-, VDC-_REF

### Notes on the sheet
- Vlinear= 1000
- VOUT = +/-2V Differntial
- G=1/602, 1/1000
- float ADJ pin for Gain = 1/602
- Vin max range= 1000V max
- (near R24) Charge bucket
- Cap after SPDT
- Charge bucket
- Vin max range= 600V max
- (near R33) Charge bucket
- f3db = 10kHz
- Optimized for low side IDC_sense input VCM

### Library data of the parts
C28 C31 C176 C409 C456 = CMP-0007121-4: CAP, CERM, 2.2 uF, 16 V, +/- 10%, X7R, 0603; Manufacturer: Taiyo Yuden; TaMin_C: -55°C; Polarized: N; SizeAreaWB_mm2: 4.68; Value1: Unknown; U/M: EA; Value: 2.2uF; TaMax_C: 125°C; SizeZ_mm: 1; SizeX_mm: 1.6; SizeY_mm: 0.8; SizeArea_mm2: 1.28; AEC Category: Q200
C29 C30 C177 C443 C457 = CMP-0006659-2: as C243 on sheet TIDA-1606-Middle-Side-E7
C32 C175 C444 C455 = CMP-0006309-2: CAP, CERM, 1000 pF, 50 V, +/- 5%, C0G/NP0, AEC-Q200 Grade 1, 0402; Manufacturer: TDK; TaMin_C: -55°C; Polarized: N; SizeAreaWB_mm2: 3; Value1: Unknown; U/M: EA; Value: 1000pF; TaMax_C: 125°C; SizeZ_mm: 0.6; SizeX_mm: 1; SizeY_mm: 0.5; Cap_Case: 0402; AEC Qualified: Y; Cap_F: 1nF; AEC Category: Q200
C33 C342 = CMP-0006412-2: CAP, CERM, 1000 pF, 50 V, +/- 5%, C0G/NP0, 0402; Manufacturer: MuRata; TaMin_C: -55°C; Polarized: N; SizeAreaWB_mm2: 3; Value1: Unknown; U/M: EA; Value: 1000pF; TaMax_C: 125°C; SizeZ_mm: 0.6; SizeX_mm: 1; SizeY_mm: 0.5; Cap_Case: 0402; Cap_F: 1nF; AEC Category: Q200
C35 C454 = CMP-0006673-2: CAP, CERM, 1000 pF, 50 V, +/- 10%, X7R, 0402; Manufacturer: MuRata; TaMin_C: -55°C; Polarized: N; SizeAreaWB_mm2: 3; Value1: Unknown; U/M: EA; Value: 1000pF; TaMax_C: 125°C; SizeZ_mm: 0.6; SizeX_mm: 1; SizeY_mm: 0.5; Cap_Case: 0402; Cap_F: 1nF; AEC Category: Q200
C286 C292 = CMP-0006327-2: CAP, CERM, 0.015 uF, 50 V, +/- 10%, X7R, AEC-Q200 Grade 1, 0402; Manufacturer: TDK; TaMin_C: -55°C; ESR_ohm: 0.2162; Polarized: N; SizeAreaWB_mm2: 3; Value1: 0.2162 ohm; U/M: EA; TaMax_C: 125°C; SizeZ_mm: 0.6; SizeX_mm: 1; SizeY_mm: 0.5; Cap_Case: 0402; AEC Qualified: Y; Cap_F: 15nF; IRMS_A: 379.389mA; AEC Category: Q200
C346 C360 C446 = CMP-0008377-2: CAP, CERM, 22 uF, 10 V, +/- 20%, X7R, 0805; Manufacturer: MuRata; SizeY_mm: 1.25; Cap_Case: 0805; SizeArea_mm2: 2.5; AEC Qualified: N; AEC Category: Q200; ValueDisplayed: 22uF; TaMin_C: -55°C; SizeAreaWB_mm2: 6.75; Value1: Unknown; U/M: EA; Value: 22uF; TaMax_C: 125°C; SizeZ_mm: 1.45; SizeX_mm: 2
L11 = CMP-0100992-1: WE-PMI SMT Power Multilayer Inductor, size 0603, 2.2uH, 0.8A, 375mOhm; Manufacturer: Wurth Elektronik; Case/Size Code: 0603; Inductance Tolerance: 20%; Q Factor: 15; Saturation Current: 0.28A; Self Resonant Frequency: 80MHz; Type: Low RDC
R19 R28 R29 R37 = CMP-0065359-1: RES, 15.0 k, .1%, .063 W, AEC-Q200 Grade 0, 0402; Manufacturer: Panasonic; Power_W: 63mW; TempCo: 25 ppm/C; Value_Code: 15k0; U/M: EA; Value: 15.0k; EIA_Code: E192; Tolerance_%: 0.1%; Res_ohm: 15k; SizeX_mm: 1.0; SizeY_mm: 0.5; SizeZ_mm: 0.6; Value2: .063W; AEC Qualified: Y; VDC_V: 50V; AEC Grade: 0; AEC Category: Q200
R20 R26 R27 R30 = CMP-0026656-1: RES, 100, 1%, 0.1 W, 0402; Manufacturer: Panasonic; Power_W: 100mW; TempCo: 100 ppm/C; Value_Code: 100R; U/M: EA; Value: 100; EIA_Code: E96; SizeX_mm: 1; SizeY_mm: 0.5; SizeZ_mm: 0.6; Value2: 0.1W; VDC_V: 50V; AEC Category: Q200
R21 R31 = CMP-0027004-2: as R361 on sheet TIDA-1606-Middle-Side-E7
R22 R25 R32 R34 = CMP-0077124-1: as R255 on sheet TIDA-1606-Middle-Side-E7
R23 = CMP-0078244-2: as R250 on sheet TIDA-1606-Middle-Side-E7
R24 R33 = CMP-0026283-2: as R273 on sheet TIDA-1606-Middle-Side-E7
TP10 = CMP-0055148-2: Test Point, Multipurpose, Black, TH; Manufacturer: Keystone Electronics; CNHeader: FALSE; ContactFinish: Silver; Green_REACh: Passed; Green_Lifecycle: Active; CT: TRUE
U24 U63 = CMP-0044881-2: Manufacturer: Texas Instruments; SizeZ_mm: 3.55mm; Standoff Height: 0.1mm; AEC Category: Q200; CompType: IC
U61 = CMP-0121707-1: as U8 on sheet TIDA-1606-Middle-Side-E7
U62 = CMP-0123146-1: Ultra-Small, 1.5W, 5.0V, 5kVRMS Isolation, Industrial DC/DC Module; Manufacturer: Texas Instruments; SizeZ_mm: 2.6mm; AEC Qualified: No; Max Supply Voltage: 5.5V; Min Supply Voltage: 4.5V; Nominal Supply Current: 7-545mA; Number Of Outputs: 1; Output Type: AdjustableProgrammable; Output Voltage: 5/5.5V; Standoff Height: 0.1mm; Switching Frequency: 76MHz; Switching Topology: Boost; TaMax_C: +125°C; TaMin_C: -40°C; TJmax_C: +150°C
